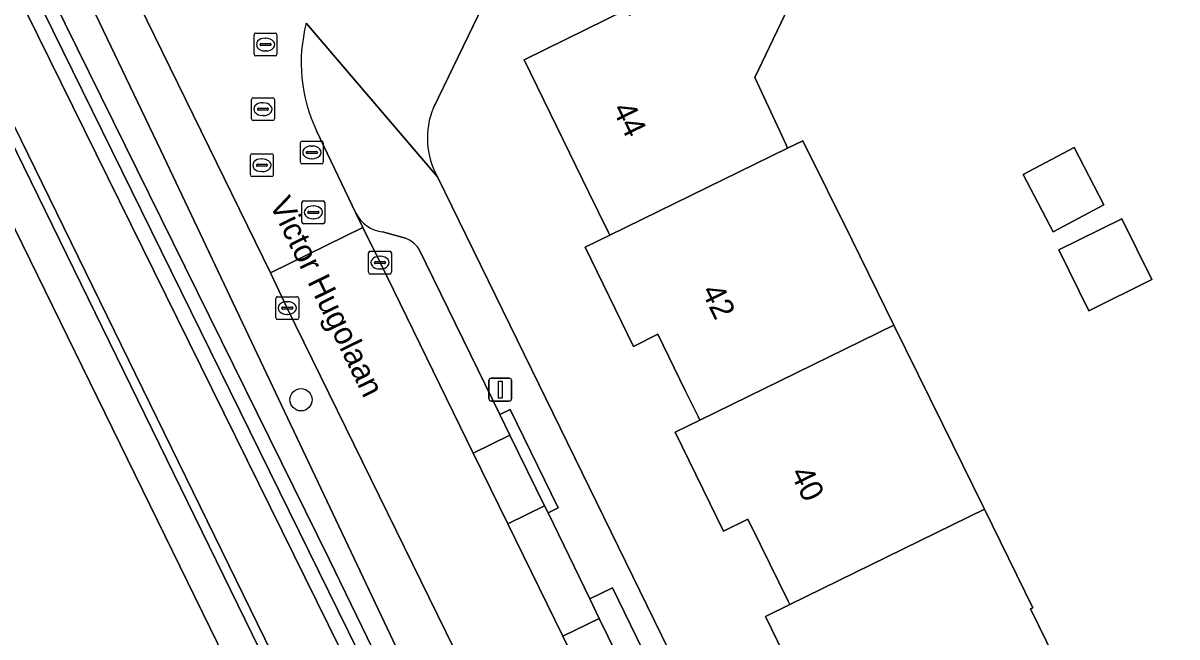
# Model space of a CAD drawing. Extents: x 160455 to 162082, y 388339 to 389736.
# Drawn here: x 160648.2 to 160698.8, y 388848.5 to 388875.4 of the extents above; entities that cross this region are included whole.
import ezdxf

# ---------------------------------------------------------------- set-up
doc = ezdxf.new("R2010")
doc.units = 0
for name, color, linetype in [('IMGEO_Boom', 7, 'Continuous'), ('IMGEO_Erf', 7, 'Continuous'), ('IMGEO_Groenvoorziening', 7, 'Continuous'), ('IMGEO_Haag', 7, 'Continuous'), ('IMGEO_Kolk', 7, 'Continuous'), ('IMGEO_Lichtmast', 7, 'Continuous'), ('IMGEO_Oever', 7, 'Continuous'), ('IMGEO_Openbare_ruimte_label', 7, 'Continuous'), ('IMGEO_Pand', 7, 'Continuous'), ('IMGEO_Pand_nummerreeks', 7, 'Continuous'), ('IMGEO_Parkeervlak_open', 7, 'Continuous'), ('IMGEO_Rijbaan_lokaal_gesloten', 7, 'Continuous'), ('IMGEO_Rijbaan_lokaal_open', 7, 'Continuous'), ('IMGEO_Rioolput', 7, 'Continuous'), ('IMGEO_Voetpad_open', 7, 'Continuous'), ('IMGEO_Waterloop', 7, 'Continuous')]:
    doc.layers.add(name, color=color, linetype=linetype)

msp = doc.modelspace()

# ---------------------------------------------------------------- linework, layer by layer
at = {"layer": 'IMGEO_Boom'}
msp.add_circle((160660.41, 388858.885), 0.489, dxfattribs=at)
at = {"layer": 'IMGEO_Erf'}
for points in [[(160626.224, 388910.601), (160605.955, 388923.367), (160604.958, 388924.006), (160591.062, 388933.242), (160554.786, 388954.994), (160549.577, 388958.117), (160548.847, 388958.571), (160547.705, 388955.023), (160547.57, 388954.603), (160547.996, 388954.609), (160548.691, 388954.505), (160549.504, 388954.293), (160553.273, 388951.494), (160551.28, 388947.987), (160550.48, 388945.512), (160506.381, 388848.187), (160613.222, 388781.291), (160619.273, 388780.316), (160676.573, 388807.682), (160664.626, 388832.146)], [(160695.563, 388867.425), (160693.349, 388866.242), (160692.041, 388868.75), (160694.277, 388869.921)], [(160697.668, 388864.144), (160694.908, 388862.784), (160693.595, 388865.45), (160696.355, 388866.81)]]:
    msp.add_lwpolyline(points, close=True, dxfattribs=at)
for points in [[(160690.994, 388922.84), (160686.612, 388913.819), (160666.21, 388871.668)], [(160682.063, 388876.722), (160680.283, 388872.993), (160681.274, 388870.861), (160681.651, 388870.048), (160681.722, 388869.896), (160682.393, 388870.224), (160684.526, 388865.893), (160686.368, 388862.153), (160688.497, 388857.831), (160690.263, 388854.244), (160690.338, 388854.092), (160692.463, 388849.779), (160692.355, 388849.726), (160694.126, 388846.13), (160694.234, 388846.183), (160694.309, 388846.03), (160696.442, 388841.699), (160696.334, 388841.646), (160697.222, 388839.843), (160698.11, 388838.041), (160698.184, 388837.89), (160699.781, 388838.674)], [(160682.863, 388845.047), (160680.746, 388849.393), (160681.824, 388849.921), (160681.75, 388850.072), (160680.534, 388852.538), (160679.979, 388853.662), (160678.914, 388853.137), (160676.801, 388857.464), (160677.878, 388857.992), (160677.804, 388858.144), (160677.24, 388859.296), (160676.036, 388861.756), (160674.964, 388861.219), (160672.853, 388865.561), (160673.932, 388866.088), (160673.858, 388866.239), (160673.02, 388867.951), (160670.176, 388873.761), (160674.662, 388875.965)], [(160666.392, 388868.639), (160693.93, 388812.297)]]:
    msp.add_lwpolyline(points, dxfattribs=at)
msp.add_arc((160669.402, 388870.34), 3.458, 157.4114, 209.4657, dxfattribs=at)
at = {"layer": 'IMGEO_Groenvoorziening'}
for points in [[(160571.444, 388750), (160571.754, 388750.166), (160572.065, 388750.329), (160607.803, 388767.824), (160687.247, 388806.714), (160686.973, 388807.274), (160686.045, 388809.17), (160684.847, 388811.633), (160677.31, 388827.125), (160668.584, 388844.978), (160659.808, 388862.897), (160659.071, 388864.445), (160648.25, 388886.548), (160638.47, 388906.585), (160629.688, 388924.586), (160620.814, 388942.765), (160619.643, 388945.116), (160619.032, 388946.319), (160618.392, 388947.991), (160617.059, 388948.01), (160612.318, 388945.878)], [(160632.719, 388914.731), (160654.274, 388869.794), (160679.394, 388816.794), (160677.9, 388815.979), (160631.061, 388910.967)], [(160626.224, 388910.601), (160664.626, 388832.146), (160676.573, 388807.682), (160619.273, 388780.316)]]:
    msp.add_lwpolyline(points, dxfattribs=at)
for points in [[(160678.293, 388808.574), (160628.33, 388910.796), (160628.082, 388911.372), (160627.729, 388911.891), (160627.283, 388912.333), (160626.762, 388912.683), (160626.574, 388912.777), (160608.695, 388923.959), (160608.477, 388923.597), (160626.439, 388912.364), (160626.539, 388912.317), (160627.025, 388912.014), (160627.436, 388911.616), (160627.756, 388911.141), (160627.97, 388910.61), (160677.93, 388808.386)], [(160627.97, 388910.61), (160627.756, 388911.141), (160627.436, 388911.616), (160627.025, 388912.014), (160626.539, 388912.317), (160626.439, 388912.364), (160608.477, 388923.597), (160608.695, 388923.959), (160626.574, 388912.777), (160626.762, 388912.683), (160627.283, 388912.333), (160627.729, 388911.891), (160628.082, 388911.372), (160628.33, 388910.796), (160678.293, 388808.574), (160677.93, 388808.386)]]:
    msp.add_lwpolyline(points, close=True, dxfattribs=at)
at = {"layer": 'IMGEO_Haag'}
msp.add_lwpolyline([(160678.293, 388808.574), (160628.33, 388910.796), (160628.082, 388911.372), (160627.729, 388911.891), (160627.283, 388912.333), (160626.762, 388912.683), (160626.574, 388912.777), (160608.695, 388923.959), (160608.477, 388923.597), (160626.439, 388912.364), (160626.539, 388912.317), (160627.025, 388912.014), (160627.436, 388911.616), (160627.756, 388911.141), (160627.97, 388910.61), (160677.93, 388808.386)], close=True, dxfattribs=at)
at = {"layer": 'IMGEO_Kolk'}
for p, q in [((160663.369, 388864.463), (160663.369, 388865.315)), ((160663.444, 388865.389), (160664.296, 388865.389)), ((160664.37, 388865.315), (160664.37, 388864.463)), ((160663.628, 388864.883), (160663.628, 388864.895)), ((160664.066, 388864.846), (160663.668, 388864.846)), ((160663.671, 388864.932), (160664.069, 388864.932)), ((160663.857, 388865.169), (160663.882, 388865.169)), ((160664.112, 388864.895), (160664.112, 388864.883)), ((160664.296, 388864.389), (160663.444, 388864.389)), ((160663.88, 388864.609), (160663.855, 388864.609)), ((160659.306, 388862.471), (160659.306, 388863.323)), ((160659.381, 388863.397), (160660.233, 388863.397)), ((160660.307, 388863.323), (160660.307, 388862.471)), ((160659.565, 388862.891), (160659.565, 388862.903)), ((160660.003, 388862.854), (160659.605, 388862.854)), ((160659.608, 388862.94), (160660.006, 388862.94)), ((160659.794, 388863.177), (160659.819, 388863.177)), ((160660.049, 388862.903), (160660.049, 388862.891)), ((160660.233, 388862.397), (160659.381, 388862.397)), ((160659.817, 388862.617), (160659.792, 388862.617))]:
    msp.add_line(p, q, dxfattribs=at)
for points in [[(160663.369, 388864.463), (160663.369, 388865.315)], [(160663.444, 388865.389), (160664.296, 388865.389)], [(160664.37, 388865.315), (160664.37, 388864.463)], [(160664.296, 388864.389), (160663.444, 388864.389)], [(160659.306, 388862.471), (160659.306, 388863.323)], [(160659.381, 388863.397), (160660.233, 388863.397)], [(160660.307, 388863.323), (160660.307, 388862.471)], [(160660.233, 388862.397), (160659.381, 388862.397)]]:
    msp.add_lwpolyline(points, dxfattribs=at)
for centre, radius, start, end in [((160663.446, 388865.313), 0.0765, 91.552, 178.448), ((160663.446, 388865.313), 0.0765, 91.552, 178.448), ((160664.294, 388865.313), 0.0765, 1.552, 88.448), ((160664.294, 388865.313), 0.0765, 1.552, 88.448), ((160663.668, 388864.892), 0.0403, 85.8775, 175.7526), ((160663.665, 388864.882), 0.0366, 178.938, 274.7102), ((160664.069, 388864.889), 0.043, 264.8664, 352.4533), ((160664.073, 388864.894), 0.0386, 1.7309, 96.639), ((160663.446, 388864.465), 0.0765, 181.552, 268.448), ((160663.446, 388864.465), 0.0765, 181.552, 268.448), ((160664.294, 388864.465), 0.0765, 271.552, 358.448), ((160664.294, 388864.465), 0.0765, 271.552, 358.448), ((160659.383, 388863.321), 0.0765, 91.552, 178.448), ((160659.383, 388863.321), 0.0765, 91.552, 178.448), ((160660.231, 388863.321), 0.0765, 1.552, 88.448), ((160660.231, 388863.321), 0.0765, 1.552, 88.448), ((160659.605, 388862.9), 0.0403, 85.8775, 175.7526), ((160659.602, 388862.89), 0.0366, 178.938, 274.7102), ((160660.006, 388862.897), 0.043, 264.8664, 352.4533), ((160660.01, 388862.902), 0.0386, 1.7309, 96.639), ((160659.383, 388862.473), 0.0765, 181.552, 268.448), ((160659.383, 388862.473), 0.0765, 181.552, 268.448), ((160660.231, 388862.473), 0.0765, 271.552, 358.448), ((160660.231, 388862.473), 0.0765, 271.552, 358.448)]:
    msp.add_arc(centre, radius, start, end, dxfattribs=at)
for centre, major_axis, ratio, start_param, end_param in [((160663.856, 388864.889), (-0.387, 0.002), 0.722429, 4.712389, 7.853982), ((160663.881, 388864.889), (-0.39, 0.002), 0.717154, 1.570796, 4.712389), ((160659.793, 388862.897), (-0.387, 0.002), 0.722429, 4.712389, 7.853982), ((160659.818, 388862.897), (-0.39, 0.002), 0.717154, 1.570796, 4.712389)]:
    msp.add_ellipse(centre, major_axis=major_axis, ratio=ratio, start_param=start_param, end_param=end_param, dxfattribs=at)
at = {"layer": 'IMGEO_Lichtmast'}
for p, q in [((160668.642, 388858.929), (160668.642, 388859.729)), ((160668.642, 388859.729), (160668.642, 388858.929)), ((160668.742, 388859.829), (160669.532, 388859.829)), ((160669.532, 388859.829), (160668.742, 388859.829)), ((160669.632, 388859.729), (160669.632, 388858.929)), ((160669.632, 388858.929), (160669.632, 388859.729)), ((160669.532, 388858.829), (160668.742, 388858.829)), ((160668.742, 388858.829), (160669.532, 388858.829))]:
    msp.add_line(p, q, dxfattribs=at)
msp.add_lwpolyline([(160669.062, 388859.704), (160669.212, 388859.704), (160669.212, 388858.954), (160669.062, 388858.954), (160669.062, 388859.704)], dxfattribs=at)
for centre, start, end in [((160668.742, 388859.729), 90, 180), ((160668.742, 388859.729), 90, 180), ((160669.532, 388859.729), 0, 90), ((160669.532, 388859.729), 360, 90), ((160668.742, 388858.929), 180, 270), ((160668.742, 388858.929), 180, 270), ((160669.532, 388858.929), 270, 0), ((160669.532, 388858.929), 270, 0)]:
    msp.add_arc(centre, 0.1, start, end, dxfattribs=at)
at = {"layer": 'IMGEO_Oever'}
for points in [[(160631.061, 388910.967), (160677.9, 388815.979), (160679.394, 388816.794), (160654.274, 388869.794), (160632.719, 388914.731)], [(160631.643, 388912.704), (160661.664, 388851.883), (160678.46, 388817.242)], [(160677.947, 388817.037), (160665.072, 388843.464), (160646.51, 388881.205), (160632.136, 388910.404)]]:
    msp.add_lwpolyline(points, dxfattribs=at)
at = {"layer": 'IMGEO_Pand'}
for points in [[(160682.063, 388876.722), (160676.271, 388879.53), (160676.188, 388879.367), (160676.525, 388879.22), (160674.812, 388875.699), (160674.662, 388875.965), (160670.176, 388873.761), (160673.02, 388867.951), (160673.858, 388866.239), (160673.932, 388866.088), (160681.722, 388869.896), (160681.651, 388870.048), (160681.274, 388870.861), (160680.283, 388872.993)], [(160681.722, 388869.896), (160673.932, 388866.088), (160672.853, 388865.561), (160674.964, 388861.219), (160676.036, 388861.756), (160677.24, 388859.296), (160677.804, 388858.144), (160677.878, 388857.992), (160686.368, 388862.153), (160684.526, 388865.893), (160682.393, 388870.224)], [(160692.041, 388868.75), (160693.349, 388866.242), (160695.563, 388867.425), (160694.277, 388869.921)], [(160694.908, 388862.784), (160697.668, 388864.144), (160696.355, 388866.81), (160693.595, 388865.45)], [(160686.368, 388862.153), (160677.878, 388857.992), (160676.801, 388857.464), (160678.914, 388853.137), (160679.979, 388853.662), (160680.534, 388852.538), (160681.75, 388850.072), (160681.824, 388849.921), (160690.338, 388854.092), (160690.263, 388854.244), (160688.497, 388857.831)], [(160690.338, 388854.092), (160681.824, 388849.921), (160680.746, 388849.393), (160682.863, 388845.047), (160683.936, 388845.579), (160685.362, 388842.685), (160685.708, 388841.982), (160685.78, 388841.835), (160694.309, 388846.03), (160694.234, 388846.183), (160694.126, 388846.13), (160692.355, 388849.726), (160692.463, 388849.779)]]:
    msp.add_lwpolyline(points, close=True, dxfattribs=at)
at = {"layer": 'IMGEO_Parkeervlak_open'}
for points in [[(160662.809, 388867.047), (160663.112, 388866.432), (160663.869, 388864.889), (160667.952, 388856.548), (160669.562, 388857.336), (160669.119, 388858.241), (160665.569, 388865.495)], [(160664.985, 388865.953), (160663.981, 388866.239)]]:
    msp.add_lwpolyline(points, dxfattribs=at)
for points in [[(160669.562, 388857.336), (160667.952, 388856.548), (160669.467, 388853.454), (160671.076, 388854.242)], [(160671.227, 388853.933), (160671.076, 388854.242), (160669.467, 388853.454), (160671.877, 388848.532), (160673.47, 388849.311), (160673.055, 388850.162)], [(160673.47, 388849.311), (160671.877, 388848.532), (160672.683, 388846.886), (160673.407, 388845.402), (160675, 388846.179)]]:
    msp.add_lwpolyline(points, close=True, dxfattribs=at)
for centre, radius, start, end in [((160664.161, 388867.754), 1.526, 207.6177, 263.216), ((160664.585, 388864.842), 1.181, 33.581, 70.2086)]:
    msp.add_arc(centre, radius, start, end, dxfattribs=at)
at = {"layer": 'IMGEO_Rijbaan_lokaal_gesloten'}
msp.add_lwpolyline([(160673.407, 388845.402), (160672.683, 388846.886), (160671.877, 388848.532), (160669.467, 388853.454), (160667.952, 388856.548), (160663.869, 388864.889), (160663.112, 388866.432), (160659.071, 388864.445), (160659.808, 388862.897), (160668.584, 388844.978), (160677.31, 388827.125), (160684.847, 388811.633), (160686.045, 388809.17), (160686.973, 388807.274), (160691.057, 388809.275), (160689.791, 388811.87), (160687.896, 388815.74), (160681.336, 388829.151)], close=True, dxfattribs=at)
at = {"layer": 'IMGEO_Rijbaan_lokaal_open'}
msp.add_lwpolyline([(160653.478, 388886.003), (160652.578, 388887.837), (160652.468, 388888.063), (160652.243, 388888.526), (160648.25, 388886.548), (160659.071, 388864.445), (160663.112, 388866.432), (160662.809, 388867.047), (160661.094, 388870.656)], dxfattribs=at)
msp.add_arc((160667.308, 388873.637), 6.892, 165.391, 205.6237, dxfattribs=at)
at = {"layer": 'IMGEO_Rioolput'}
for p, q in [((160658.355, 388874.01), (160658.355, 388874.862)), ((160658.43, 388874.936), (160659.282, 388874.936)), ((160659.356, 388874.862), (160659.356, 388874.01)), ((160658.614, 388874.43), (160658.614, 388874.442)), ((160659.052, 388874.393), (160658.654, 388874.393)), ((160658.657, 388874.479), (160659.055, 388874.479)), ((160658.843, 388874.716), (160658.868, 388874.716)), ((160659.098, 388874.442), (160659.098, 388874.43)), ((160659.282, 388873.936), (160658.43, 388873.936)), ((160658.866, 388874.156), (160658.841, 388874.156)), ((160658.241, 388871.18), (160658.241, 388872.032)), ((160658.316, 388872.106), (160659.168, 388872.106)), ((160658.729, 388871.886), (160658.754, 388871.886)), ((160659.242, 388872.032), (160659.242, 388871.18)), ((160658.5, 388871.6), (160658.5, 388871.612)), ((160658.938, 388871.563), (160658.54, 388871.563)), ((160658.543, 388871.649), (160658.941, 388871.649)), ((160658.752, 388871.326), (160658.727, 388871.326)), ((160658.984, 388871.612), (160658.984, 388871.6)), ((160659.168, 388871.106), (160658.316, 388871.106)), ((160660.383, 388869.286), (160660.383, 388870.138)), ((160660.458, 388870.212), (160661.31, 388870.212)), ((160660.871, 388869.992), (160660.896, 388869.992)), ((160661.384, 388870.138), (160661.384, 388869.286)), ((160658.196, 388868.728), (160658.196, 388869.58)), ((160658.271, 388869.654), (160659.123, 388869.654)), ((160658.684, 388869.434), (160658.709, 388869.434)), ((160659.197, 388869.58), (160659.197, 388868.728)), ((160660.642, 388869.706), (160660.642, 388869.718)), ((160661.08, 388869.669), (160660.682, 388869.669)), ((160660.685, 388869.755), (160661.083, 388869.755)), ((160660.894, 388869.432), (160660.869, 388869.432)), ((160661.126, 388869.718), (160661.126, 388869.706)), ((160658.455, 388869.148), (160658.455, 388869.16)), ((160658.893, 388869.111), (160658.495, 388869.111)), ((160658.498, 388869.197), (160658.896, 388869.197)), ((160658.707, 388868.874), (160658.682, 388868.874)), ((160658.939, 388869.16), (160658.939, 388869.148)), ((160661.31, 388869.212), (160660.458, 388869.212)), ((160659.123, 388868.654), (160658.271, 388868.654)), ((160660.449, 388866.662), (160660.449, 388867.514)), ((160660.524, 388867.588), (160661.376, 388867.588)), ((160660.937, 388867.368), (160660.962, 388867.368)), ((160661.45, 388867.514), (160661.45, 388866.662)), ((160660.708, 388867.082), (160660.708, 388867.094)), ((160661.146, 388867.045), (160660.748, 388867.045)), ((160660.751, 388867.131), (160661.149, 388867.131)), ((160660.96, 388866.808), (160660.935, 388866.808)), ((160661.192, 388867.094), (160661.192, 388867.082)), ((160661.376, 388866.588), (160660.524, 388866.588))]:
    msp.add_line(p, q, dxfattribs=at)
for points in [[(160658.355, 388874.01), (160658.355, 388874.862)], [(160658.43, 388874.936), (160659.282, 388874.936)], [(160659.356, 388874.862), (160659.356, 388874.01)], [(160659.282, 388873.936), (160658.43, 388873.936)], [(160658.241, 388871.18), (160658.241, 388872.032)], [(160658.316, 388872.106), (160659.168, 388872.106)], [(160659.242, 388872.032), (160659.242, 388871.18)], [(160659.168, 388871.106), (160658.316, 388871.106)], [(160660.383, 388869.286), (160660.383, 388870.138)], [(160660.458, 388870.212), (160661.31, 388870.212)], [(160661.384, 388870.138), (160661.384, 388869.286)], [(160658.196, 388868.728), (160658.196, 388869.58)], [(160658.271, 388869.654), (160659.123, 388869.654)], [(160659.197, 388869.58), (160659.197, 388868.728)], [(160661.31, 388869.212), (160660.458, 388869.212)], [(160659.123, 388868.654), (160658.271, 388868.654)], [(160660.449, 388866.662), (160660.449, 388867.514)], [(160660.524, 388867.588), (160661.376, 388867.588)], [(160661.45, 388867.514), (160661.45, 388866.662)], [(160661.376, 388866.588), (160660.524, 388866.588)]]:
    msp.add_lwpolyline(points, dxfattribs=at)
for centre, radius, start, end in [((160658.432, 388874.86), 0.0765, 91.552, 178.448), ((160658.432, 388874.86), 0.0765, 91.552, 178.448), ((160659.28, 388874.86), 0.0765, 1.552, 88.448), ((160659.28, 388874.86), 0.0765, 1.552, 88.448), ((160658.654, 388874.439), 0.0403, 85.8775, 175.7526), ((160658.651, 388874.429), 0.0366, 178.938, 274.7102), ((160659.055, 388874.436), 0.043, 264.8664, 352.4533), ((160659.059, 388874.441), 0.0386, 1.7309, 96.639), ((160658.432, 388874.012), 0.0765, 181.552, 268.448), ((160658.432, 388874.012), 0.0765, 181.552, 268.448), ((160659.28, 388874.012), 0.0765, 271.552, 358.448), ((160659.28, 388874.012), 0.0765, 271.552, 358.448), ((160658.318, 388872.03), 0.0765, 91.552, 178.448), ((160658.318, 388872.03), 0.0765, 91.552, 178.448), ((160659.166, 388872.03), 0.0765, 1.552, 88.448), ((160659.166, 388872.03), 0.0765, 1.552, 88.448), ((160658.54, 388871.609), 0.0403, 85.8775, 175.7526), ((160658.537, 388871.599), 0.0366, 178.938, 274.7102), ((160658.941, 388871.606), 0.043, 264.8664, 352.4533), ((160658.945, 388871.611), 0.0386, 1.7309, 96.639), ((160658.318, 388871.182), 0.0765, 181.552, 268.448), ((160658.318, 388871.182), 0.0765, 181.552, 268.448), ((160659.166, 388871.182), 0.0765, 271.552, 358.448), ((160659.166, 388871.182), 0.0765, 271.552, 358.448), ((160660.46, 388870.136), 0.0765, 91.552, 178.448), ((160660.46, 388870.136), 0.0765, 91.552, 178.448), ((160661.308, 388870.136), 0.0765, 1.552, 88.448), ((160661.308, 388870.136), 0.0765, 1.552, 88.448), ((160658.273, 388869.578), 0.0765, 91.552, 178.448), ((160658.273, 388869.578), 0.0765, 91.552, 178.448), ((160659.121, 388869.578), 0.0765, 1.552, 88.448), ((160659.121, 388869.578), 0.0765, 1.552, 88.448), ((160660.46, 388869.288), 0.0765, 181.552, 268.448), ((160660.46, 388869.288), 0.0765, 181.552, 268.448), ((160660.682, 388869.715), 0.0403, 85.8775, 175.7526), ((160660.679, 388869.705), 0.0366, 178.938, 274.7102), ((160661.083, 388869.712), 0.043, 264.8664, 352.4533), ((160661.087, 388869.717), 0.0386, 1.7309, 96.639), ((160661.308, 388869.288), 0.0765, 271.552, 358.448), ((160661.308, 388869.288), 0.0765, 271.552, 358.448), ((160658.495, 388869.157), 0.0403, 85.8775, 175.7526), ((160658.492, 388869.147), 0.0366, 178.938, 274.7102), ((160658.896, 388869.154), 0.043, 264.8664, 352.4533), ((160658.9, 388869.159), 0.0386, 1.7309, 96.639), ((160658.273, 388868.73), 0.0765, 181.552, 268.448), ((160658.273, 388868.73), 0.0765, 181.552, 268.448), ((160659.121, 388868.73), 0.0765, 271.552, 358.448), ((160659.121, 388868.73), 0.0765, 271.552, 358.448), ((160660.526, 388867.512), 0.0765, 91.552, 178.448), ((160660.526, 388867.512), 0.0765, 91.552, 178.448), ((160661.374, 388867.512), 0.0765, 1.552, 88.448), ((160661.374, 388867.512), 0.0765, 1.552, 88.448), ((160660.748, 388867.091), 0.0403, 85.8775, 175.7526), ((160660.745, 388867.081), 0.0366, 178.938, 274.7102), ((160661.149, 388867.088), 0.043, 264.8664, 352.4533), ((160661.153, 388867.093), 0.0386, 1.7309, 96.639), ((160660.526, 388866.664), 0.0765, 181.552, 268.448), ((160660.526, 388866.664), 0.0765, 181.552, 268.448), ((160661.374, 388866.664), 0.0765, 271.552, 358.448), ((160661.374, 388866.664), 0.0765, 271.552, 358.448)]:
    msp.add_arc(centre, radius, start, end, dxfattribs=at)
for centre, major_axis, ratio, start_param, end_param in [((160658.842, 388874.436), (-0.387, 0.002), 0.722429, 4.712389, 7.853982), ((160658.867, 388874.436), (-0.39, 0.002), 0.717154, 1.570796, 4.712389), ((160658.728, 388871.606), (-0.387, 0.002), 0.722429, 4.712389, 7.853982), ((160658.753, 388871.606), (-0.39, 0.002), 0.717154, 1.570796, 4.712389), ((160660.87, 388869.712), (-0.387, 0.002), 0.722429, 4.712389, 7.853982), ((160660.895, 388869.712), (-0.39, 0.002), 0.717154, 1.570796, 4.712389), ((160658.683, 388869.154), (-0.387, 0.002), 0.722429, 4.712389, 7.853982), ((160658.708, 388869.154), (-0.39, 0.002), 0.717154, 1.570796, 4.712389), ((160660.936, 388867.088), (-0.387, 0.002), 0.722429, 4.712389, 7.853982), ((160660.961, 388867.088), (-0.39, 0.002), 0.717154, 1.570796, 4.712389)]:
    msp.add_ellipse(centre, major_axis=major_axis, ratio=ratio, start_param=start_param, end_param=end_param, dxfattribs=at)
at = {"layer": 'IMGEO_Voetpad_open'}
for points in [[(160666.21, 388871.668), (160686.612, 388913.819)], [(160666.392, 388868.639), (160660.639, 388875.375)], [(160660.639, 388875.375), (160666.392, 388868.639)], [(160661.094, 388870.656), (160662.809, 388867.047)], [(160693.93, 388812.297), (160666.392, 388868.639)], [(160663.981, 388866.239), (160664.985, 388865.953)], [(160665.569, 388865.495), (160669.119, 388858.241), (160669.569, 388858.46), (160671.676, 388854.152), (160671.227, 388853.933), (160673.055, 388850.162), (160674.044, 388850.645), (160676.149, 388846.333), (160675.16, 388845.85), (160677.034, 388842.069), (160678.023, 388842.551), (160680.132, 388838.224), (160679.143, 388837.742), (160681.023, 388834.001), (160682.017, 388834.472), (160684.203, 388829.858), (160683.209, 388829.387), (160685.343, 388825.087), (160686.333, 388825.567), (160688.575, 388820.944), (160687.585, 388820.464), (160690.214, 388815.112)]]:
    msp.add_lwpolyline(points, dxfattribs=at)
for points in [[(160669.569, 388858.46), (160669.119, 388858.241), (160669.562, 388857.336), (160671.076, 388854.242), (160671.227, 388853.933), (160671.676, 388854.152)], [(160674.044, 388850.645), (160673.055, 388850.162), (160673.47, 388849.311), (160675, 388846.179), (160675.16, 388845.85), (160676.149, 388846.333)]]:
    msp.add_lwpolyline(points, close=True, dxfattribs=at)
for centre, radius, start, end in [((160667.308, 388873.637), 6.892, 165.391, 205.6237), ((160669.402, 388870.34), 3.458, 157.4114, 209.4657), ((160664.161, 388867.754), 1.526, 207.6177, 263.216), ((160664.585, 388864.842), 1.181, 33.581, 70.2086)]:
    msp.add_arc(centre, radius, start, end, dxfattribs=at)
at = {"layer": 'IMGEO_Waterloop'}
for points in [[(160678.46, 388817.242), (160661.664, 388851.883), (160631.643, 388912.704)], [(160632.136, 388910.404), (160646.51, 388881.205), (160665.072, 388843.464), (160677.947, 388817.037)]]:
    msp.add_lwpolyline(points, dxfattribs=at)

# ---------------------------------------------------------------- texts
at = {"layer": 'IMGEO_Openbare_ruimte_label'}
msp.add_text('Victor Hugolaan', height=1, rotation=296.0272, dxfattribs=at).set_placement((160659.008, 388867.46))
at = {"layer": 'IMGEO_Pand_nummerreeks'}
for s, p in [('44', (160674.026, 388871.623)), ('42', (160677.921, 388863.652)), ('40', (160681.821, 388855.674))]:
    msp.add_text(s, height=1, rotation=296.0465, dxfattribs=at).set_placement(p)

doc.saveas('drawing.dxf')
